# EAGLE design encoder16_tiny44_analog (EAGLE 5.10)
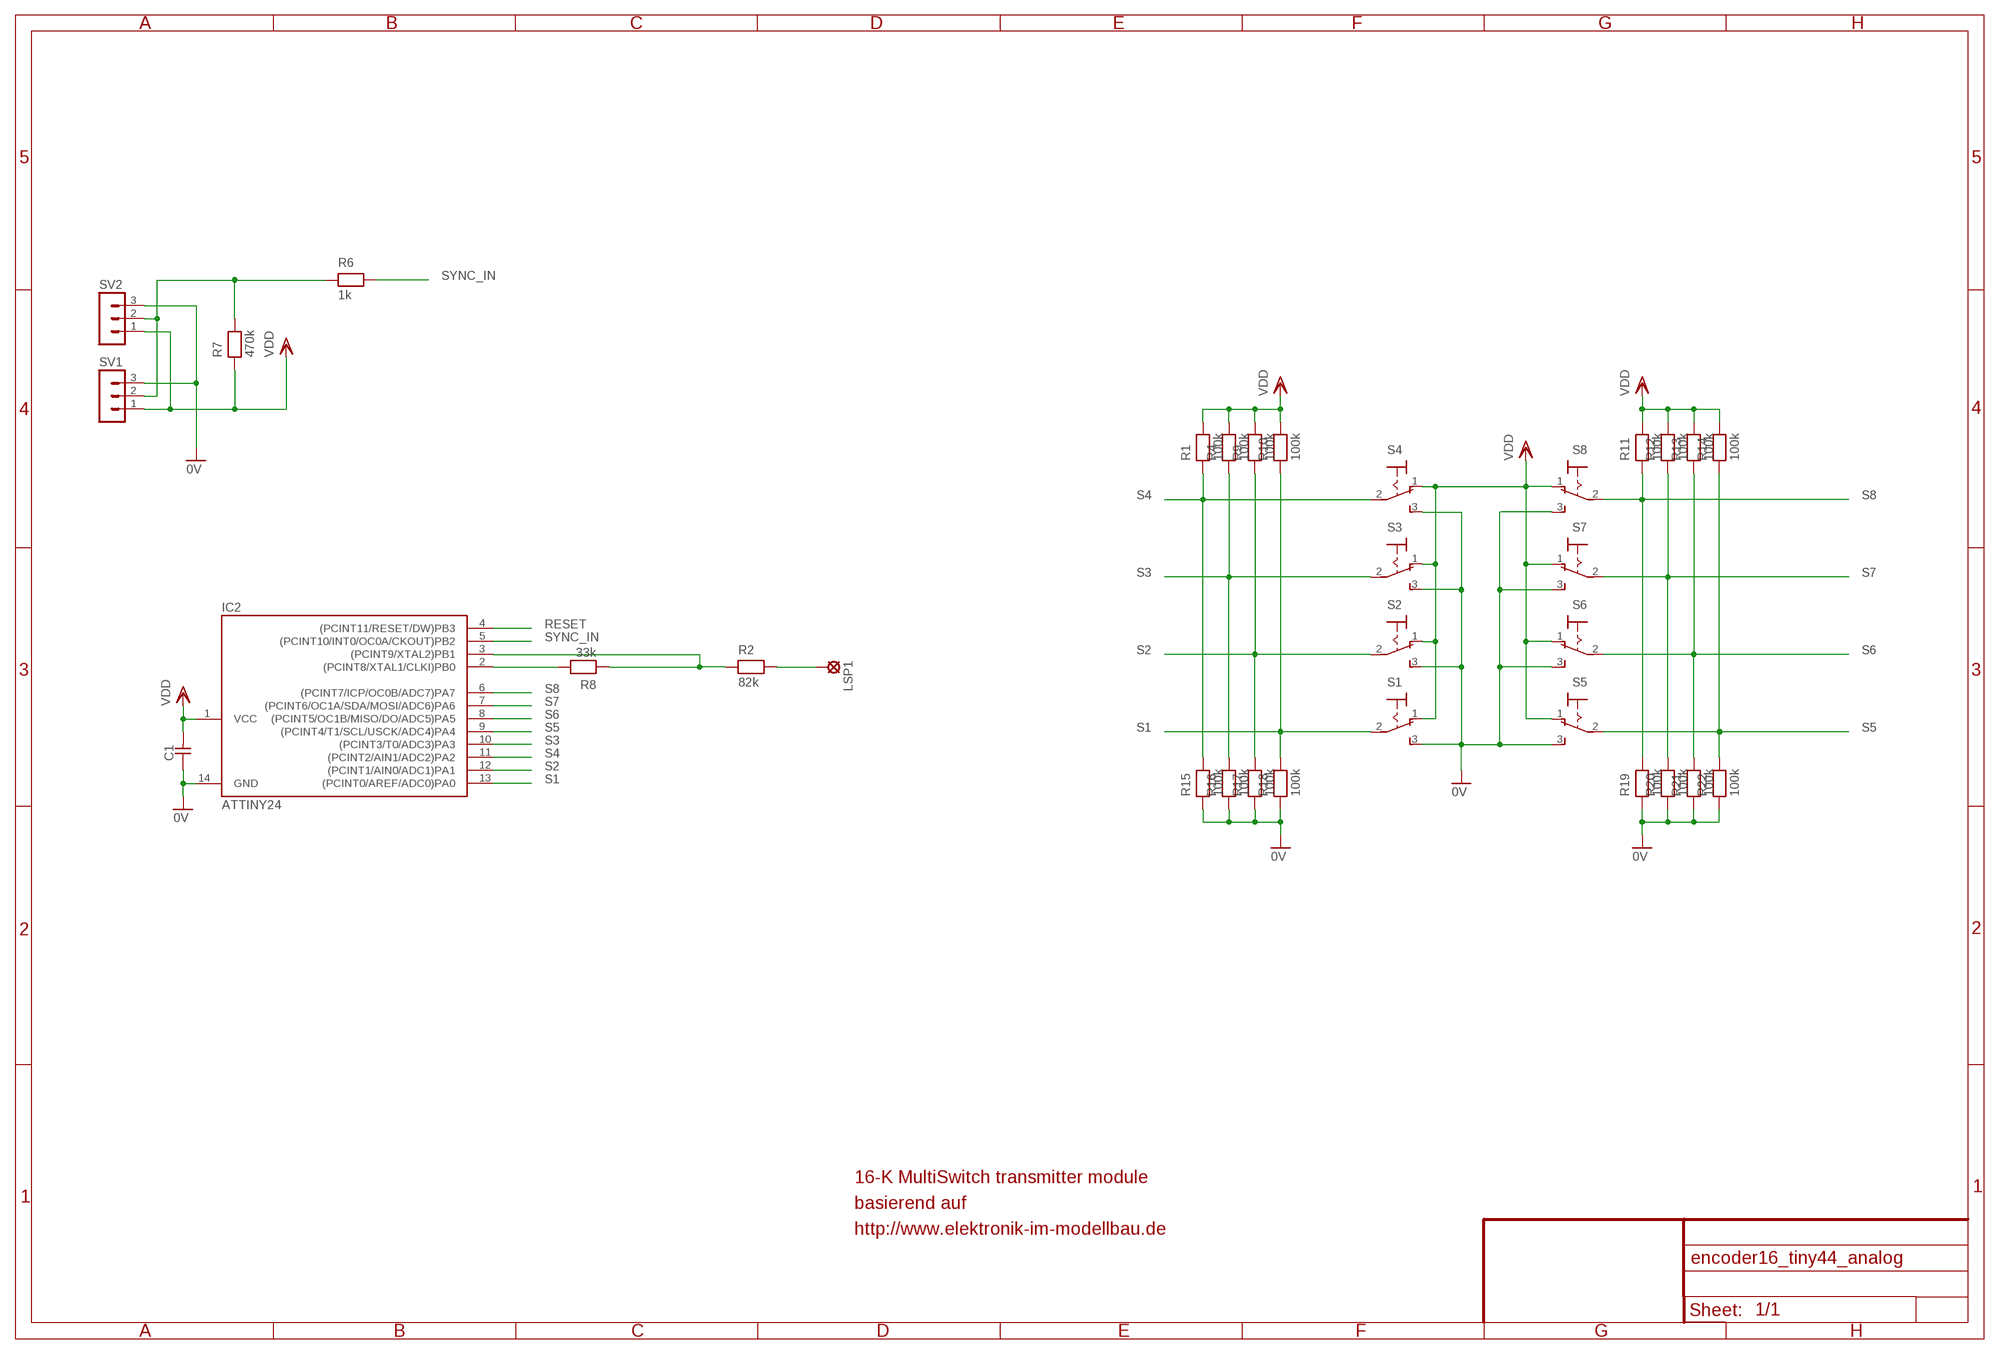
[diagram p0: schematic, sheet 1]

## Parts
C1  CAP-SMDG5  [C-GRID5]
IC2  ATTINY24  ATTINY24/44/84-SSU  [SOIC14]
LSP1  LSP10  [LSP10]
R1  100k  RES07.5  [R-7,5]
R2  82k  RES0805  [0805]
R4  100k  RES07.5  [R-7,5]
R6  1k  RES0805  [0805]
R7  470k  RES0805  [0805]
R8  33k  RES1206  [1206]
R9  100k  RES1206  [1206]
R10  100k  RES0805  [0805]
R11  100k  RES1206  [1206]
R12  100k  RES0805  [0805]
R13  100k  RES0805  [0805]
R14  100k  RES0805  [0805]
R15  100k  RES1206  [1206]
R16  100k  RES0805  [0805]
R17  100k  RES0805  [0805]
R18  100k  RES0805  [0805]
R19  100k  RES07.5  [R-7,5]
R20  100k  RES07.5  [R-7,5]
R21  100k  RES1206  [1206]
R22  100k  RES0805  [0805]
S1  M9040P  [M9040P]
S2  M9040P  [M9040P]
S3  M9040P  [M9040P]
S4  M9040P  [M9040P]
S5  M9040P  [M9040P]
S6  M9040P  [M9040P]
S7  M9040P  [M9040P]
S8  M9040P  [M9040P]
SV1  MA03-1  [MA03-1]
SV2  MA03-1  [MA03-1]

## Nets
0V: C1.1 IC2.14(GND) R15.1 R16.1 R17.1 R18.1 R19.1 R20.1 R21.1 R22.1 S1.3(S) S2.3(S) S3.3(S) S4.3(S) S5.3(S) S6.3(S) S7.3(S) S8.3(S) SV1.3 SV2.3
N$1: IC2.3((PCINT9/XTAL2)PB1) R2.1 R8.1
N$2: IC2.2((PCINT8/XTAL1/CLKI)PB0) R8.2
N$3: R6.1 R7.2 SV1.2 SV2.2
N$5: LSP1.MP R2.2
RESET: IC2.4((PCINT11/RESET/DW)PB3)
S1: IC2.13((PCINT0/AREF/ADC0)PA0) R10.1 R18.2 S1.2(P)
S2: IC2.12((PCINT1/AIN0/ADC1)PA1) R9.1 R17.2 S2.2(P)
S3: IC2.10((PCINT3/T0/ADC3)PA3) R4.1 R16.2 S3.2(P)
S4: IC2.11((PCINT2/AIN1/ADC2)PA2) R1.1 R15.2 S4.2(P)
S5: IC2.9((PCINT4/T1/SCL/USCK/ADC4)PA4) R14.1 R22.2 S5.2(P)
S6: IC2.8((PCINT5/OC1B/MISO/DO/ADC5)PA5) R13.1 R21.2 S6.2(P)
S7: IC2.7((PCINT6/OC1A/SDA/MOSI/ADC6)PA6) R12.1 R20.2 S7.2(P)
S8: IC2.6((PCINT7/ICP/OC0B/ADC7)PA7) R11.1 R19.2 S8.2(P)
SYNC_IN: IC2.5((PCINT10/INT0/OC0A/CKOUT)PB2) R6.2
VDD: C1.2 IC2.1(VCC) R1.2 R4.2 R7.1 R9.2 R10.2 R11.2 R12.2 R13.2 R14.2 S1.1(O) S2.1(O) S3.1(O) S4.1(O) S5.1(O) S6.1(O) S7.1(O) S8.1(O) SV1.1 SV2.1

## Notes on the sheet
- 16-K MultiSwitch transmitter module
- basierend auf
- http://www.elektronik-im-modellbau.de

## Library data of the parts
C1 = scaleart:CAP-SMD: unipolare Kondensatoren
IC2 = scaleart:ATTINY24/44/84
LSP1 = solpad:LSP10: SOLDER PAD
R1 R4 R9-R22 = firefly-lbr_v2_5:RES: Widerstand
R2 = scaleart_v5:RES: Widerstand
R6-R8 = scaleart:RES: Widerstand
S1-S8 = switch:M9040P: TOGGLE SWITCH Marquardt
SV1 SV2 = con-lstb:MA03-1

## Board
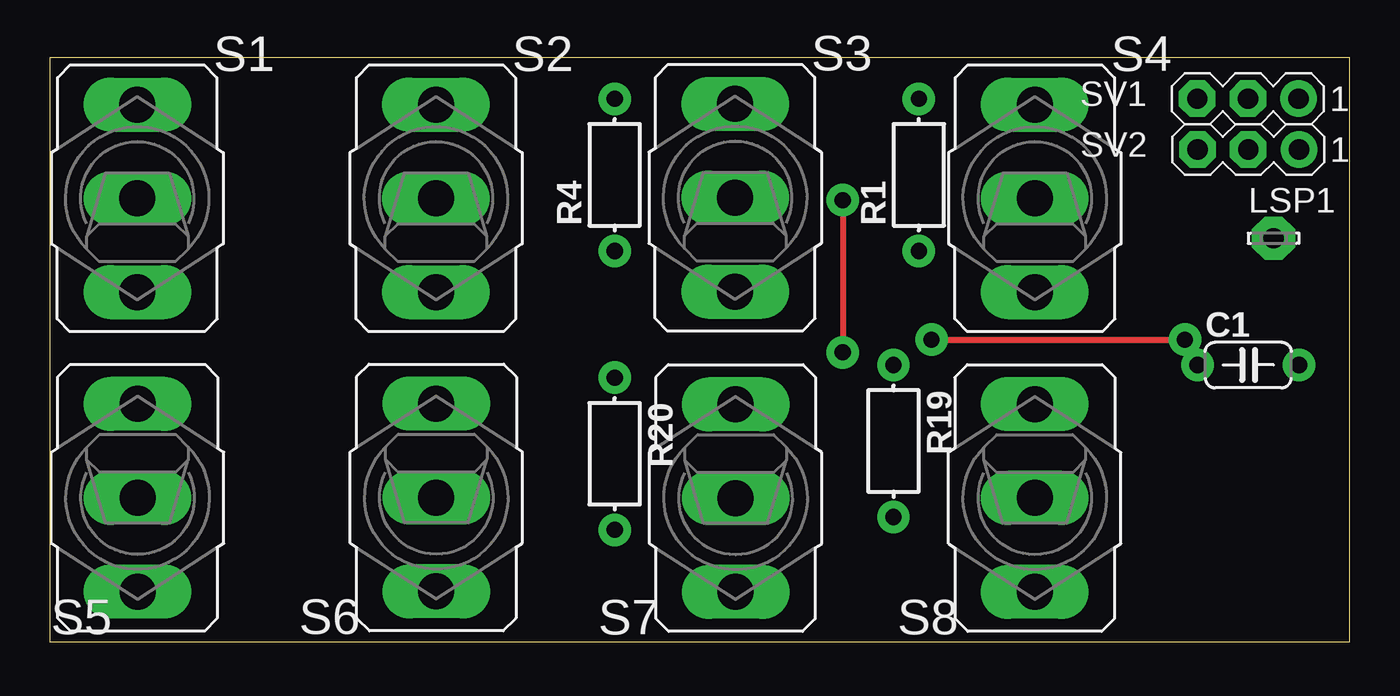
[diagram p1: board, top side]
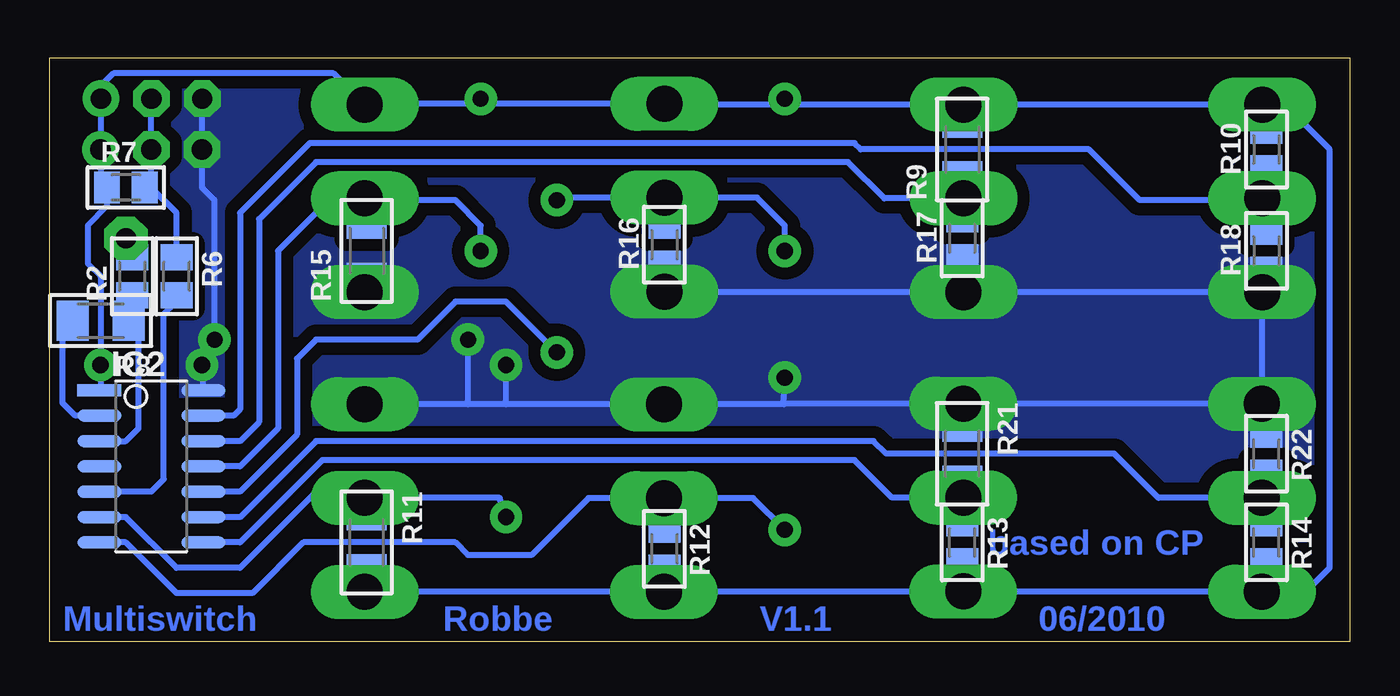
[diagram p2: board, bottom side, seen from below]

Size 65.13 x 29.27 mm. Coordinates in mm from the lower left corner, seen from the top.
Outline: 0,0 65.13,0 65.13,29.27 0,29.27 0,0
Copper layers (1*16): Top 0.035mm / dielectric 1.5mm / Bottom 0.035mm
Design rules "benji": minimum track width 16mil, minimum drill 32mil, track to track 24mil, track to pad 24mil, pad to pad 24mil, via to via 24mil, smd to smd 16mil, copper to edge 40mil, drill to drill 8mil, minimum pad ring 16mil, minimum via ring 16mil, stop-mask expansion 4mil, vias tented up to drill 0mil, thermal gap 10mil

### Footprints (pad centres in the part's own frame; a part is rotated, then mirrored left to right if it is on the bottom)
C-GRID5 = drill 0.813 round: 1 -2.54,0; 2 2.54,0
SOIC14 = smd 0.61 x 2.21: 1 -3.81,-2.603; 2 -2.54,-2.603; 3 -1.27,-2.603; 4 0,-2.603; 5 1.27,-2.603; 6 2.54,-2.603; 7 3.81,-2.603; 8 3.81,2.603; 9 2.54,2.603; 10 1.27,2.603; 11 0,2.603; 12 -1.27,2.603; 13 -2.54,2.603; 14 -3.81,2.603
LSP10 = drill 1.016 pad 2.159 octagon: MP 0,0
R-7,5 = drill 0.813 pad 1.6 round: 1 -3.81,0; 2 3.81,0
0805 = smd 1.3 x 1.6: 1 -0.95,0; 2 0.95,0
1206 = smd 1.6 x 2: 1 -1.4,0; 2 1.4,0
M9040P = drill 1.803 long: 1 0,4.699; 2 0,0; 3 0,-4.699
MA03-1 = drill 1.016 pad 1.6 round: 1 -2.54,0 | drill 1.016 pad 1.6 octagon: 2 0,0; 3 2.54,0

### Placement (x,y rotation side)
C1  60.05,13.87 0 top
IC2  60.05,8.79 270 bottom
LSP1  61.32,20.22 0 top
R1  43.54,23.4 90 top
R2  61.01,18.32 90 bottom
R4  28.3,23.4 90 top
R6  58.78,18.32 270 bottom
R7  61.32,22.76 0 bottom
R8  62.59,16.1 180 bottom
R9  19.41,24.67 90 bottom
R10  4.17,24.67 90 bottom
R11  49.26,4.98 270 bottom
R12  34.34,4.67 270 bottom
R13  19.41,4.98 270 bottom
R14  4.17,4.98 270 bottom
R15  49.26,19.59 90 bottom
R16  34.34,19.91 90 bottom
R17  19.41,20.22 90 bottom
R18  4.17,19.59 90 bottom
R19  42.27,10.06 270 top
R20  28.3,9.43 270 top
R21  19.41,9.43 270 bottom
R22  4.17,9.43 270 bottom
S1  4.38,22.22 0 top
S2  19.35,22.22 0 top
S3  34.34,22.25 0 top
S4  49.36,22.22 0 top
S5  4.39,7.22 180 top
S6  19.37,7.23 180 top
S7  34.36,7.21 180 top
S8  49.36,7.21 180 top
SV1  60.04,27.21 180 top
SV2  60.05,24.67 180 top

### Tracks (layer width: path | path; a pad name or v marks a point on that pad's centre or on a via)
0V  (via drill 0.81 pad 1.52)
  Top 0.305: v44.18,15.14 v56.88,15.14 | 57.45,13.81 C1.1 56.88,14.51
  Bottom 0.305: SV1.3 57.5,24.68 SV2.3 57.51,22.76 56.88,22.13 v56.88,15.14 56.88,14.51 | S1.3 S2.3 | S2.3 34.31,17.53 S3.3 | S1.3 S5.3 | S2.3 19.37,17.51 | S3.3 34.36,17.53 | 42.27,11.91 S7.3 28.37,11.91 R20.1 | 42.27,11.91 44.18,11.91 | 44.18,11.91 S8.3 | S3.3 34.37,17.53 | R18.1 4.17,17.73 S1.3 | R22.1 4.17,11.7 S5.3 | R21.1 19.41,11.89 S6.3 | R17.1 19.41,17.59 S2.3 | R16.1 S3.3 | 42.27,11.91 R19.1 | R15.1 49.26,17.62 S4.3 | 44.18,11.91 v44.18,15.14 | IC2.14 57.45,13.81 | S6.3 28.27,11.93 28.3,11.97 | S6.3 4.41,11.93 S5.3
  pour Bottom (isolate 0.305, no thermals): -0.27,29.75 -0.27,-0.1 65.77,-0.1 65.77,29.75
N$1
  Bottom 0.305: IC2.3 61.32,10.06 60.69,10.7 60.69,15.14 61.32,15.78 | 61.32,16.41 R8.1
  Bottom 0.406: 61.32,15.78 61.32,16.41 60.69,16.41 60.69,15.78 61.01,15.78 R2.1
N$2
  Bottom 0.305: IC2.2 63.86,11.33 64.5,11.97 64.5,15.91 R8.2
N$3
  Bottom 0.305: SV1.2 60.05,27.2 SV2.2 60.05,22.76 | 60.05,22.76 60.05,22.45 R7.2 60.05,22.76 | 60.05,22.76 58.78,21.49 R6.1
N$5
  Bottom 0.406: R2.2 61.32,19.27 LSP1.MP
S1
  Bottom 0.305: S1.2 4.38,22.13 10.52,22.13 13.06,24.67 24.49,24.67 24.81,24.99 52.12,24.99 55.61,21.49 55.61,11.65 55.93,11.33 IC2.13 | R10.1 4.17,22.43 S1.2 | R18.2 4.17,22.02 S1.2
S2
  Bottom 0.305: S2.2 23.32,22.22 25.13,24.03 51.8,24.03 54.65,21.18 54.65,11.02 55.61,10.06 IC2.12 | R9.1 19.41,22.29 S2.2 | R17.2 19.41,22.16 S2.2
S3  (via drill 0.81 pad 1.52)
  Top 0.305: v39.73,22.13 v39.73,14.51
  Bottom 0.305: R16.2 S3.2 | R4.1 28.3,20.86 29.7,22.25 S3.2 | S3.2 39.61,22.25 v39.73,22.13 | v39.73,14.51 42.27,17.05 44.81,17.05 46.72,15.14 51.8,15.14 52.75,14.19 52.75,10.38 55.61,7.52 IC2.10
S4
  Bottom 0.305: R1.1 43.54,20.86 44.81,22.13 49.26,22.13 S4.2 | R15.2 49.26,22.12 S4.2 | IC2.11 55.61,8.79 53.7,10.7 53.7,19.59 51.07,22.22 S4.2
S5
  Bottom 0.305: S5.2 9.58,7.22 11.79,9.43 23.22,9.43 23.86,10.06 51.8,10.06 55.61,6.25 IC2.9 | R14.1 4.17,7 S5.2 | R22.2 4.17,7.44 S5.2
S6
  Bottom 0.305: S6.2 22.93,7.24 24.81,9.11 51.48,9.11 55.61,4.98 IC2.8 | R13.1 19.41,7.19 S6.2 | R21.2 19.41,7.28 S6.2
S7
  Bottom 0.305: S7.2 38.14,7.21 41,4.35 44.18,4.35 44.81,4.98 52.43,4.98 54.97,2.44 58.78,2.44 61.32,4.98 IC2.7 | R12.1 34.34,7.18 S7.2 | S7.2 29.89,7.21 R20.2
S8
  Bottom 0.305: R11.1 49.26,7.11 S8.2 | S8.2 42.6,7.21 R19.2 | S8.2 49.58,7.21 | IC2.6 61.32,6.25 58.78,3.71 55.61,3.71 51.8,7.52 49.67,7.52 S8.2
SYNC_IN
  Bottom 0.305: IC2.5 60.05,7.52 59.42,8.16 59.42,16.41 58.78,17.05 R6.2
VDD
  Bottom 0.305: 62.58,24.68 SV1.1 62.58,27.86 61.96,28.48 50.91,28.48 S4.1 49.33,26.95 43.54,26.95 | 62.58,24.68 SV2.1 | S2.1 S1.1 4.03,26.57 | S2.1 28.3,26.92 | 28.3,26.92 34.31,26.92 S3.1 43.54,26.95 | S5.1 2.19,2.52 1,3.71 1,24.67 2.9,26.57 4.03,26.57 | S5.1 19.41,2.52 | 19.41,2.52 34.02,2.52 | 34.02,2.52 S8.1 49.26,2.61 R11.2 | 34.03,2.51 S7.1 34.34,2.54 R12.2 | 34.02,2.52 34.03,2.51 | 34.03,2.51 34.03,2.46 34.02,2.44 34.65,2.44 | 19.41,2.52 19.4,2.54 S6.1 19.41,2.58 R13.2 | 4.03,26.57 4.17,26.57 R10.2 | R14.2 4.17,2.74 S5.1 | R9.2 19.41,26.86 S2.1 | 28.3,26.92 R4.2 | 43.54,26.95 R1.2 | 62.58,24.68 62.58,23.07 R7.1 62.27,21.81 63.23,20.86 63.23,18.95 62.59,18.32 C1.2 62.59,12.6 IC2.1

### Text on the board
Bottom: based on CP | 06/2010 | V1.1 | Robbe | Multiswitch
